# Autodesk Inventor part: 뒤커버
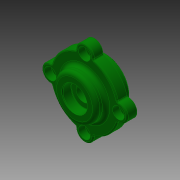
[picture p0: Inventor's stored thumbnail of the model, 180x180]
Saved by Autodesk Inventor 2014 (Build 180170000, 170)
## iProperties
Created: 2016-05
Part Number: 뒤커버
Document SubType Name: Modeling
Designer: mduedu
Density: 2.71 g/cm^3
Material: 알루미늄 6061
Appearance: 진녹색
Author: mduedu
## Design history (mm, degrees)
sketch "스케치1"
  geometry: C1 r 20 at (0, 0); C2 r 27.5 at (0, 0); 1 further point
  constraints: 2 centre point, 2 coincident
  dimensions: "d33" = 55 diameter of C2; "d34" = 40 diameter of C1
extrude "돌출1" new body sketch "스케치1" distance "d0" = 8; taper "d1" = 0 deg
extrude "돌출2" join sketch "스케치1" distance "d2" = 8; taper "d3" = 0 deg; dims "d35" = 9, "d36" = 0
sketch "스케치6"
  geometry: C1 r 17.5 at (0, 0); 2 further points
  constraints: 2 coincident, 1 centre point
  dimensions: "d42" = 35 diameter of C1
extrude "돌출4" join sketch "스케치6" distance "d43" = 8; taper "d44" = 0 deg
sketch "스케치4"
  geometry: L1 (0, -9)-(0, 16); L2 (-15, -9)-(-15, 0); L3 (-15, 0)-(-10, 0); L4 (-10, 0)-(-10, 3); L5 (-10, 3)-(-6, 3); L6 (-6, 3)-(-6, 8.7); L7 (-6, 8.7)-(-10, 8.7); L8 (-10, 8.7)-(-10, 16); L9 (20, -9)-(-20, -9) reference; L10 (17.5, 16)-(-17.5, 16) reference; 1 further point
  constraints: 16 end point, 6 parallel, 3 point on line, 2 midpoint, 2 perpendicular, 1 vertical
  dimensions: "d15" = 30 diameter of L2 L1; "d16" = 20 diameter of L8 L1; "d18" = 9 distance of L2.start L2.end; "d19" = 3 distance of L3.end L4.end; "d20" = 20 diameter of L4 L1; "d21" = 12 diameter of L6 L1; "d45" = 7.3 distance of L7.end L8.end
revolve "회전1" sketch "스케치4" stored, may be unused: angle "d22" = 90 deg
fillet "모깎기2" dims "d23" = 3
fillet "모깎기3" dims "d24" = 0.3
chamfer "모따기2" distance "d46" = 1; stored, may be unused: second distance "d47" = 2, angle "d48" = 45 deg
sketch "스케치7"
  geometry: C1 r 7 at (0, 27.5); 2 further points
  constraints: 3 vertical alignment, 1 centre point, 2 other
  dimensions: "d54" = 14 diameter of C1
extrude "돌출5" join sketch "스케치7" stored distance "d55" = 10; taper "d56" = 0 deg
fillet "모깎기6" dims "d57" = 1
sketch "스케치10"
  geometry: C1 r 17.5 at (0, 0) reference; A1 r 27.5 centre (0, 0) between (26.395, 7.718) and (7.718, 26.395) reference; A2 r 1 centre (7.999, 27.355) between (6.999, 27.373) and (7.718, 26.395) reference; A3 r 7 centre (0, 27.5) between (6.999, 27.373) and (-6.999, 27.373) reference; A4 r 1 centre (-7.999, 27.355) between (-7.718, 26.395) and (-6.999, 27.373) reference; A5 r 27.5 centre (0, 0) between (-7.718, 26.395) and (-26.395, 7.718) reference; A6 r 1 centre (-27.355, 7.999) between (-27.373, 6.999) and (-26.395, 7.718) reference; A7 r 7 centre (-27.5, 0) between (-27.373, 6.999) and (-27.373, -6.999) reference; A8 r 1 centre (-27.355, -7.999) between (-26.395, -7.718) and (-27.373, -6.999) reference; A9 r 27.5 centre (0, 0) between (-26.395, -7.718) and (-7.718, -26.395) reference; A10 r 1 centre (-7.999, -27.355) between (-6.999, -27.373) and (-7.718, -26.395) reference; A11 r 7 centre (0, -27.5) between (-6.999, -27.373) and (6.999, -27.373) reference; A12 r 1 centre (7.999, -27.355) between (7.718, -26.395) and (6.999, -27.373) reference; A13 r 27.5 centre (0, 0) between (7.718, -26.395) and (26.395, -7.718) reference; A14 r 1 centre (27.355, -7.999) between (27.373, -6.999) and (26.395, -7.718) reference; A15 r 7 centre (27.5, 0) between (27.373, -6.999) and (27.373, 6.999) reference; A16 r 1 centre (27.355, 7.999) between (26.395, 7.718) and (27.373, 6.999) reference; 4 further points
  constraints: 3 coincident
hole "구멍3" sketch "스케치10" at (0, 27.5), (-27.5, 0), (0, -27.5), (27.5, 0) diameter "d81" = 5.5; stored, may be unused: countersink angle "d85" = 90 deg, drill point angle "d87" = 118 deg; dims "d82" = 6, "d83" = 9.5, "d84" = 5.4, "d86" = 8
fillet "모깎기7" dims "d61" = 1
fillet "모깎기8" dims "d88" = 3
chamfer "모따기3" distance "d76" = 0.7; stored, may be unused: second distance "d77" = 2, angle "d78" = 30 deg
node "솔리드1"
pattern_circular "원형 패턴1" dims angle "d59" = 360 deg
node "투영된 루프1"
